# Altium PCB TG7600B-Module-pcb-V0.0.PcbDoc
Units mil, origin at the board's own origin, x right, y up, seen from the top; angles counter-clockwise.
Board outline 3892 x 2980 mil, 2 copper layers (TOP Layer, Bottom Layer), stack 12.8 mil thick; 20 components, 32 nets, 94 pads, 106 vias.
Unrouted connection lines stored in the file: 1.
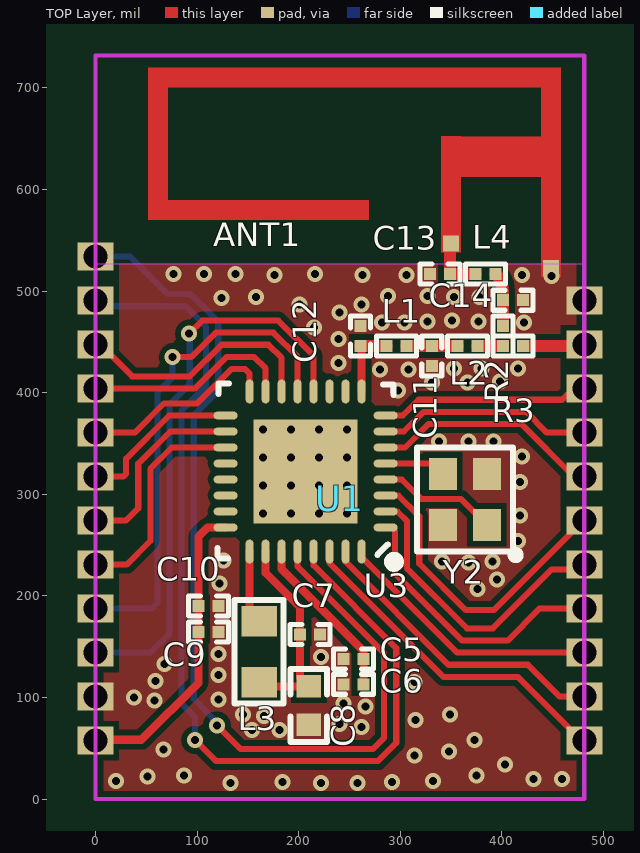
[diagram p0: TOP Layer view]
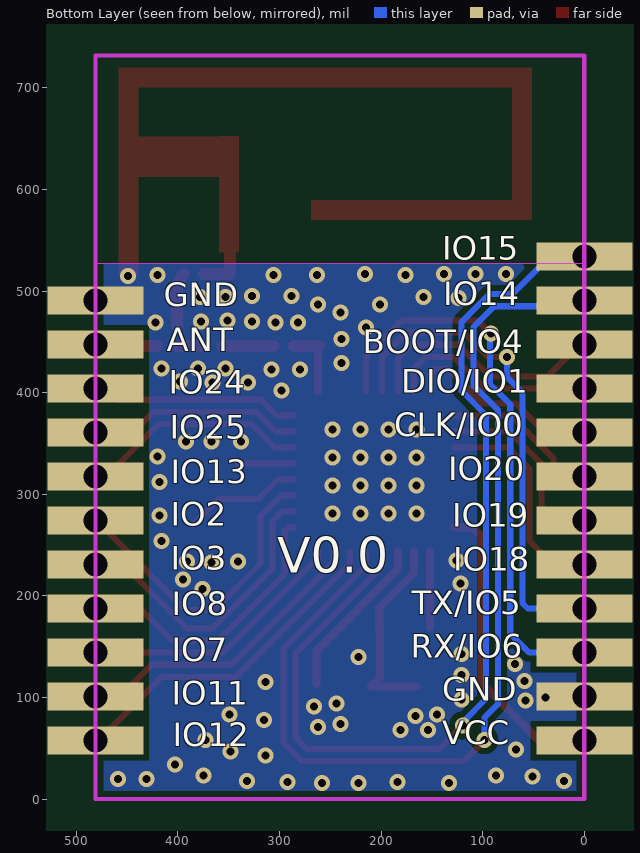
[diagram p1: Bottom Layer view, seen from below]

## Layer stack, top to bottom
TOP Layer: signal copper 1.4
Dielectric: core 10, FR-4, Dk 4.2
Bottom Layer: signal copper 1.4

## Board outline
-484.23,2533.42 3407.77,2533.42 3407.77,-446.58 -484.23,-446.58 -484.23,2533.42

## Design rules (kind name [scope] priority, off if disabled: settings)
Clearance [All] p1: gap=5.91
ComponentClearance [All] p1: gap=0 collisioncheckmode=3 verticalgap=0 showdistances=TRUE
MinimumSolderMaskSliver [All] p1: minsoldermaskwidth=1
PolygonConnect PolygonConnect_1 [All] p1: connectstyle=Direct reliefconductorwidth=10 reliefentries=4 polygonreliefangle="90 Angle"
RoutingVias [All] p1: holewidth=10 width=18 viastyle="Through Hole" minholewidth=6 minwidth=10 maxholewidth=50 maxwidth=50
SilkToSilkClearance [All] p1: silktosilkclearance=0
SilkscreenOverComponentPads SilkToSolderMaskClearance [IsPad] p1: minsilkscreentomaskgap=0
SolderMaskExpansion [All] p1: expansion=2
TestPointUsage FabricationTestPointUsage [All] p1: valid=0 allowmultiple=FALSE
Testpoint FabricationTestpoint [All] p1: side=3 testpointundercomponent=TRUE minsize=40 maxsize=100 preferedsize=60 minholesize=0 maxholesize=40 preferedholesize=32 testpointgrid=1 style=297 order=0123456789
Width [All] p1: maxlimit=100 minlimit=5 preferedwidth=6
20 further rules are at their usual default settings.

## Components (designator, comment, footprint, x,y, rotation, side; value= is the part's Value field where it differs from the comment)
ANT1 "ANTENNA" "2.4G PCB ANT-F-1" 350,547 r0 top
C5 "1uF/6.3V" C-0201 253.84,138 r0 top
C6 "0.1uF/6.3V" C-0201 253.84,113 r0 top
C7 "0.1uF/6.3V" C-0201 211,162 r180 top
C8 "4.7uF/6.3V" C-0402 210,92 r90 top
C9 "1uF/6.3V" C-0201 111.16,164.54 r0 top
C10 "0.1uF/6.3V" C-0201 111.16,190 r0 top
C11 "0.8pF/50V" C-0201 331,436.16 r90 top
C12 "0.3pF/50V" C-0201 261,455.84 r270 top
C13 "NC" C-0201 339,517 r0 top
C14 "NC" C-0201 411,491 r180 top
L1 "3.3nH" R-0201-1 296.16,446 r180 top
L2 "3.3nH" R-0201-1 366.16,446 r180 top
L3 "10uH" R-0603 161,145 r270 top
L4 "0R" R-0201-1 384,517 r0 top
R2 "0R" R-0201-1 401,455.84 r270 top
R3 "NC" R-0201-1 410.84,446 r0 top
U1 "TG7600B-Module" Module-TG7600B 240.55,295.67 r0 top locked
U3 "OM6626B" QFN32-4*4-0.4 206.77,322.42 r90 top
Y2 "32Mhz,8pF/9pF,10ppm" XD-2016 363.57,295 r90 top

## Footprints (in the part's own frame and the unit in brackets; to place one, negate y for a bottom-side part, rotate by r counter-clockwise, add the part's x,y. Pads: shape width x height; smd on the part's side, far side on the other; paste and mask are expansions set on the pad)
"2.4G PCB ANT-F-1" [mm]
  rect 0.4x0.4 smd paste-0.25 mask-0.25: 1(0,0)
  rect 0.4x0.4 smd: 2(2.501,-0.612)
  TOP Layer region: 2.611,1.662 2.611,2.676 -0.247,2.676 -0.247,1.662
  TOP Layer region: -7.581,1.08 -7.581,0.58 -2.058,0.58 -2.058,1.08
  TOP Layer region: -7.582,0.78 -7.083,0.78 -7.083,4.398 -7.582,4.398
  TOP Layer region: 2.522,3.898 2.522,4.398 -7.426,4.398 -7.426,3.898
  TOP Layer region: 2.751,4.398 2.251,4.398 2.251,-0.838 2.751,-0.838
  TOP Layer region: 0.243,2.685 -0.257,2.685 -0.257,-0.229 0.243,-0.229
C-0201 [mm]
  rect 0.3x0.3 smd: 1(-0.25,0) 2(0.25,0)
  silkscreen extent -0.5,-0.25 0.5,0.25
C-0402 [mil]
  rect 22x24 smd: 1(-19,0) 2(19,0)
  silkscreen extent -36,-18 36,18
Module-TG7600B [mm]
  rect 0.9x0.7 / inner rect 0.9x0.7 / far side rect 2.4x0.7 hole 0.6: 1(-6.11,6.05) 2(-6.11,4.95) 3(-6.11,3.85) 4(-6.11,2.75) 5(-6.11,1.65) 6(-6.11,0.55) 7(-6.11,-0.55) 8(-6.11,-1.65) 9(-6.11,-2.75) 10(-6.11,-3.85) 11(-6.11,-4.95) 12(-6.11,-6.05) 13(6.11,-6.05) 14(6.11,-4.95) 15(6.11,-3.85) 16(6.11,-2.75) 17(6.11,-1.65) 18(6.11,-0.55) 19(6.11,0.55) 20(6.11,1.65) 21(6.11,2.75) 22(6.11,3.85) 23(6.11,4.95)
  Keep-Out Layer lines w0.102: -6.11,-7.51 6.11,-7.51 6.11,11.08 -6.11,11.08 -6.11,-7.51
QFN32-4*4-0.4 [mm]
  rect 2.6x2.6 smd: 0(0,0)
  oval 0.2x0.6 smd mask+0.076: 1(-1.4,-2) 2(-1,-2) 3(-0.6,-2) 4(-0.2,-2) 5(0.2,-2) 6(0.6,-2) 7(1,-2) 8(1.4,-2) 17(1.4,2) 18(1,2) 19(0.6,2) 20(0.2,2) 21(-0.2,2) 22(-0.6,2) 23(-1,2) 24(-1.4,2)
  oval 0.6x0.2 smd mask+0.076: 9(2,-1.4) 10(2,-1) 11(2,-0.6) 12(2,-0.2) 13(2,0.2) 14(2,0.6) 15(2,1) 16(2,1.4) 25(-2,1.4) 26(-2,1) 27(-2,0.6) 28(-2,0.2) 29(-2,-0.2) 30(-2,-0.6) 31(-2,-1) 32(-2,-1.4)
  silkscreen extent -2.38,-2.34 2.2,2.2
R-0201-1 [mm]
  rect 0.3x0.3 smd: 1(-0.25,0) 2(0.25,0)
  silkscreen extent -0.5,-0.25 0.5,0.25
R-0603 [mil]
  rect 30x35 smd: 1(-30,0) 2(30,0)
  silkscreen extent -51,-24 51,24
XD-2016 [mm]
  rect 0.8x0.7 smd: 1(-0.637,-0.55) 2(0.637,0.55) 3(-0.637,0.55) 3(0.637,-0.55)
  silkscreen extent -1.5,-1.37 1.3,1.2

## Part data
C5 C6 C7 C8 C9 C10: library part C_1
C11 C12 C13 C14: library part Cap, "Capacitor"
L1 L2 L4: library part Inductor, "Inductor"
L3: library part INDUCTOR
R2 R3: library part RES
U3: library part OM6626QMHAQ
Y2: library part CRYSTAL

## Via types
v1: diameter 15.75, hole 7.87, TOP Layer to Bottom Layer, tented both sides, 106 vias

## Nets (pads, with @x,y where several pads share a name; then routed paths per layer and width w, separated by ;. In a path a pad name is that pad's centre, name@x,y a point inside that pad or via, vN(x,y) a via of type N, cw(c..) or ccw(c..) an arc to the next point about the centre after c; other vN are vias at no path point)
32M_N: U3.4 Y2.1 | length 118.2
  TOP Layer w6: U3.4 301.46,314.54 320.57,295.43 359.72,295.43 Y2.1
32M_P: U3.5 Y2.2 | length 55
  TOP Layer w6: U3.5 Y2.2@340.56,330.29
ANT: R3.2 U1.22 | length 45.4
  TOP Layer w11.81: R3.2 U1.22@466.05,446
BOOT/IO4: U1.3 U3.14 | length 240.2
  TOP Layer w6: U1.3@10.96,447.19 10.91,447.24 10.91,441.09 36,416 92.89,416 124.07,447.19 170.14,447.19 183.15,434.18 U3.14
CLK/IO00: U1.5 U3.16 | length 186.2
  TOP Layer w6: U1.5@10.91,360.63 38.63,360.63 67.44,389.44 100,389.44 133.94,423.38 147,423.38 151.65,418.72 U3.16
DIO/IO01: U1.4 U3.15 | length 196.9
  TOP Layer w6: U1.4@10.91,403.94 97.66,403.94 129.01,435.28 156,435.28 167.4,423.88 U3.15
DVDD: C5.2 C6.2 U3.27 | length 164
  TOP Layer w7.87: U3.27 183.15,226.42 263.68,145.89 C5.2 C6.2
GND: ANT1.2 C5.1 C6.1 C7.1 C8.1 C9.2 C10.2 C11.1 C12.1 C13.1 C14.1 U1.11 U1.23 U3.0 Y2.3
  other v1: 133,16 222,16 258,16 184,17 292,17 20,18 332,18 431,20 459,20 51,22 87,23 375,23 403,34 314,43 348,47 67,49 373,58 154,68 181,68 262,71 240,74 315,78 166,82 145,83 349,83 266,91 244,94 58,97 121,98 38,100 314,115 59,116 121,122 68,133 222,140 121,143 376,207 122,212 395,216 367,233 341,234 391,234 126,235 416,254 418,279 165,281.32 192.56,281.32 220.12,281.32 247.68,281.32 165,308.88 192.56,308.88 220.12,308.88 247.68,308.88 418,312 165,336.44 192.56,336.44 220.12,336.44 247.68,336.44 420,337 338,352 367,352 392,352 165,364 192.56,364 220.12,364 247.68,364 298,402 331,410 366,410 398,411 280,423 308,423 353,424 380,424 416,424 239,429 239,453 215,464 282,469 304,469 422,469 327,470 377,470 351,471 240,479 201,487 262,487 124,493 158,494 353,494 378,494 288,495 327,495 449,515 176,516 263,516 306,516 420,516 77,517 107,517 138,517 216,517
GPIO13: U1.19 U3.6 | length 216.1
  TOP Layer w6: U3.6 304.71,346.04 327.86,369.19 418.97,369.19 470.2,317.97 U1.19@470.2,317.32
IO02: U1.18 U3.3 | length 300.9
  TOP Layer w6: U3.3 298.2,298.8 318.66,278.34 318.66,231.85 364.51,186 392.16,186 470.2,264.03 U1.18@470.2,274.02
IO03/ADC: U1.17 U3.2 | length 295.8
  TOP Layer w6: U3.2@295.8,283.05 U3.2 297.12,283.05 306.76,273.41 306.76,226.92 365.67,168 391,168 449.09,226.09 465.58,226.09 U1.17@470.2,230.71
IO07/ADC: U1.15 U3.32 | length 252.8
  TOP Layer w6: U3.32 261.89,238.11 355.91,144.09 U1.15@470.2,144.09
IO08/ADC: U1.16 U3.1 | length 268.4
  TOP Layer w6: U3.1 291.55,267.3 294.85,264 294.85,221.99 360.84,156 405.6,156 437,187.4 U1.16@470.2,187.4
IO11: U1.14 U3.31 | length 289.3
  TOP Layer w6: U3.31 246.14,233.39 347.34,132.19 425.6,132.19 457,100.79 U1.14@470.2,100.79
IO12: U1.13 U3.30 | length 328.5
  TOP Layer w6: U3.30 230.39,232.3 342.41,120.28 415.72,120.28 470.2,65.8 U1.13@470.2,57.48
IO14/ADC: U1.2 U3.29 | length 966.9
  TOP Layer w6: v1(98.09,58.07) 118.85,37.32 278.02,37.32 296,55.29 296,148.57 214.65,229.93 U3.29
  Bottom Layer w6: U1.2@10.91,490.55 16.36,485.09 88.63,485.09 108.91,464.82 108.91,406.75 84.81,382.65 84.81,93.62 98.09,80.34 v1(98.09,58.07)
IO15/ADC: U1.1 U3.28 | length 950.7
  TOP Layer w6: v1(119.5,72.5) 142.78,49.22 273.09,49.22 284.09,60.22 284.09,143.64 198.9,228.84 U3.28
  Bottom Layer w6: U1.1@10.91,533.86 34.14,533.86 71,497 93.57,497 120.82,469.75 120.82,401.82 96.72,377.72 96.72,98.55 119.5,75.77 v1(119.5,72.5)
IO18: U1.8 U3.19 | length 206.6
  TOP Layer w6: U1.8@10.91,230.71 30.71,230.71 54,254 54,325.19 74.85,346.04 U3.19
IO19: U1.7 U3.18 | length 179.4
  TOP Layer w6: U1.7@10.91,274.02 30.02,274.02 42.09,286.09 42.09,330.26 73.62,361.79 U3.18
IO20: U1.6 U3.17 | length 150.9
  TOP Layer w6: U1.6@10.91,317.32 27.32,317.32 30.19,320.19 30.19,335.19 72.54,377.54 U3.17
IO24: U1.21 U3.8 | length 195.6
  TOP Layer w6: U3.8 302.54,377.54 318,393 459.26,393 U1.21@470.2,403.94
IO25: U1.20 U3.7 | length 201.2
  TOP Layer w6: U3.7 303.62,361.79 322.93,381.09 423.91,381.09 444.37,360.63 U1.20@470.2,360.63
NetANT1_1: ANT1.1 C13.2 L4.1 | length 54.2
  TOP Layer w11.81: ANT1.1@348.84,545.84 C13.2 L4.1
NetC11_2: C11.2 L1.1 L2.2 | length 50.3
  TOP Layer w11.81: L1.1 C11.2 L2.2
NetC14_2: C14.2 L4.2 R2.1 | length 53.1
  TOP Layer w11.81: L4.2 cw(c376.18,499.34) 401.16,499.34 C14.2 ; R2.1 C14.2@401,490.84
NetL2_1: L2.1 R2.2 R3.1 | length 25
  TOP Layer w11.81: L2.1 R3.1
RF: C12.2 L1.2 U3.9 | length 69.3
  TOP Layer w7.87: U3.9 C12.2@261.89,445.11
  TOP Layer w11.81: C12.2 L1.2
RX: U1.10 U3.12 | length 551
  TOP Layer w6: v1(92,458) 105,471 180,471 214.65,436.35 U3.12
  Bottom Layer w6: U1.10@10.91,144.09 54.09,144.09 72.91,162.91 72.91,388.54 92.78,408.42 92.78,457.22 v1(92,458)
SW: L3.1 U3.25 | length 74.7
  TOP Layer w7.87: L3.1@151.65,169 151.65,175 U3.25
TX: U1.9 U3.13 | length 477.5
  TOP Layer w6: v1(76,435) 94.36,435 118.46,459.09 175.07,459.09 198.9,435.27 U3.13
  Bottom Layer w6: U1.9@10.91,187.4 55.4,187.4 61,193 61,400.37 76,415.37 v1(76,435)
VBAT: C9.1 C10.1 U1.12 U3.24 | length 286.1
  TOP Layer w8: U1.12@12.82,58.45 45.45,58.45 101.32,114.32 C9.1 C10.1 101.31,258.32 110.3,267.3 U3.24
VDD1P2: C7.2 C8.2 L3.2 U3.26 | length 195.4
  TOP Layer w7.87: L3.2@165,111 C8.2 201.16,119.84 C7.2 C7.2@201.16,165 ; U3.26 167.4,222.68 201.31,188.77 C7.2@201.31,165
pads on no net: U3.10 U3.11 U3.20 U3.21 U3.22 U3.23

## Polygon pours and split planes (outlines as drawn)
GND on TOP Layer "top" (solid, remove dead copper, pour order 1000): 0,731.89 0,0 22,0 481.1,0 481.1,35 481.1,731.89 466,731.89
GND on Bottom Layer "bot" (solid, remove dead copper, pour order 1001): 0,731.89 0,0 22,0 481.1,0 481.1,35 481.1,731.89 466,731.89

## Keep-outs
Keep-Out Layer:
  pour cut-out: 0,731.89 0,527 481.1,527 481.1,731.89

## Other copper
TOP Layer:
  pour cut-out: 151.65,401.16 128.03,377.54 128.03,267.3 151.65,243.68 261.89,243.68 285.51,267.3 285.51,377.54 261.89,401.16
  pour cut-out: 137.59,154.09 139,152.69 139,130 183,130 184.41,131.41 184.41,154.09

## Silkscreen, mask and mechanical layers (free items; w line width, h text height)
Bottom Overlay:
  text "IO15" at 140,523 h40
  text "IO14" at 139,478 h40
  text "GND" at 414,477 h40
  text "ANT" at 411,433 h40
  text "BOOT/IO4" at 218,431 h40
  text "DIO/IO1" at 180,392 h40
  text "IO24" at 409,391 h40
  text "CLK/IO0" at 187,349 h40
  text "IO25" at 408,347 h40
  text "IO20" at 134,306 h40
  text "IO13" at 407,303 h40
  text "IO2" at 407,261 h40
  text "IO19" at 130,260 h40
  text "IO3" at 407,218 h40
  text "IO18" at 129,217 h40
  text "V0.0" at 302,211 h60
  text "TX/IO5" at 170,174 h40
  text "IO8" at 406,173 h40
  text "RX/IO6" at 171,131 h40
  text "IO7" at 406,128 h40
  text "GND" at 140,89 h40
  text "IO11" at 406,85 h40
  text "VCC" at 140,46 h40
  text "IO12" at 405,44 h40
Top Solder:
  lines w23.62: 39.37,34.74 39.37,18.9 440.94,18.9 440.94,68 ; 39.37,87.11 39.37,209.63 ; 39.37,442 39.37,507.09 297,507.09 ; 440.94,317 441,266 ; 440.94,420 441,413
Drill Drawing:
  text ".Legend" at 50.55,1221.06 h60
